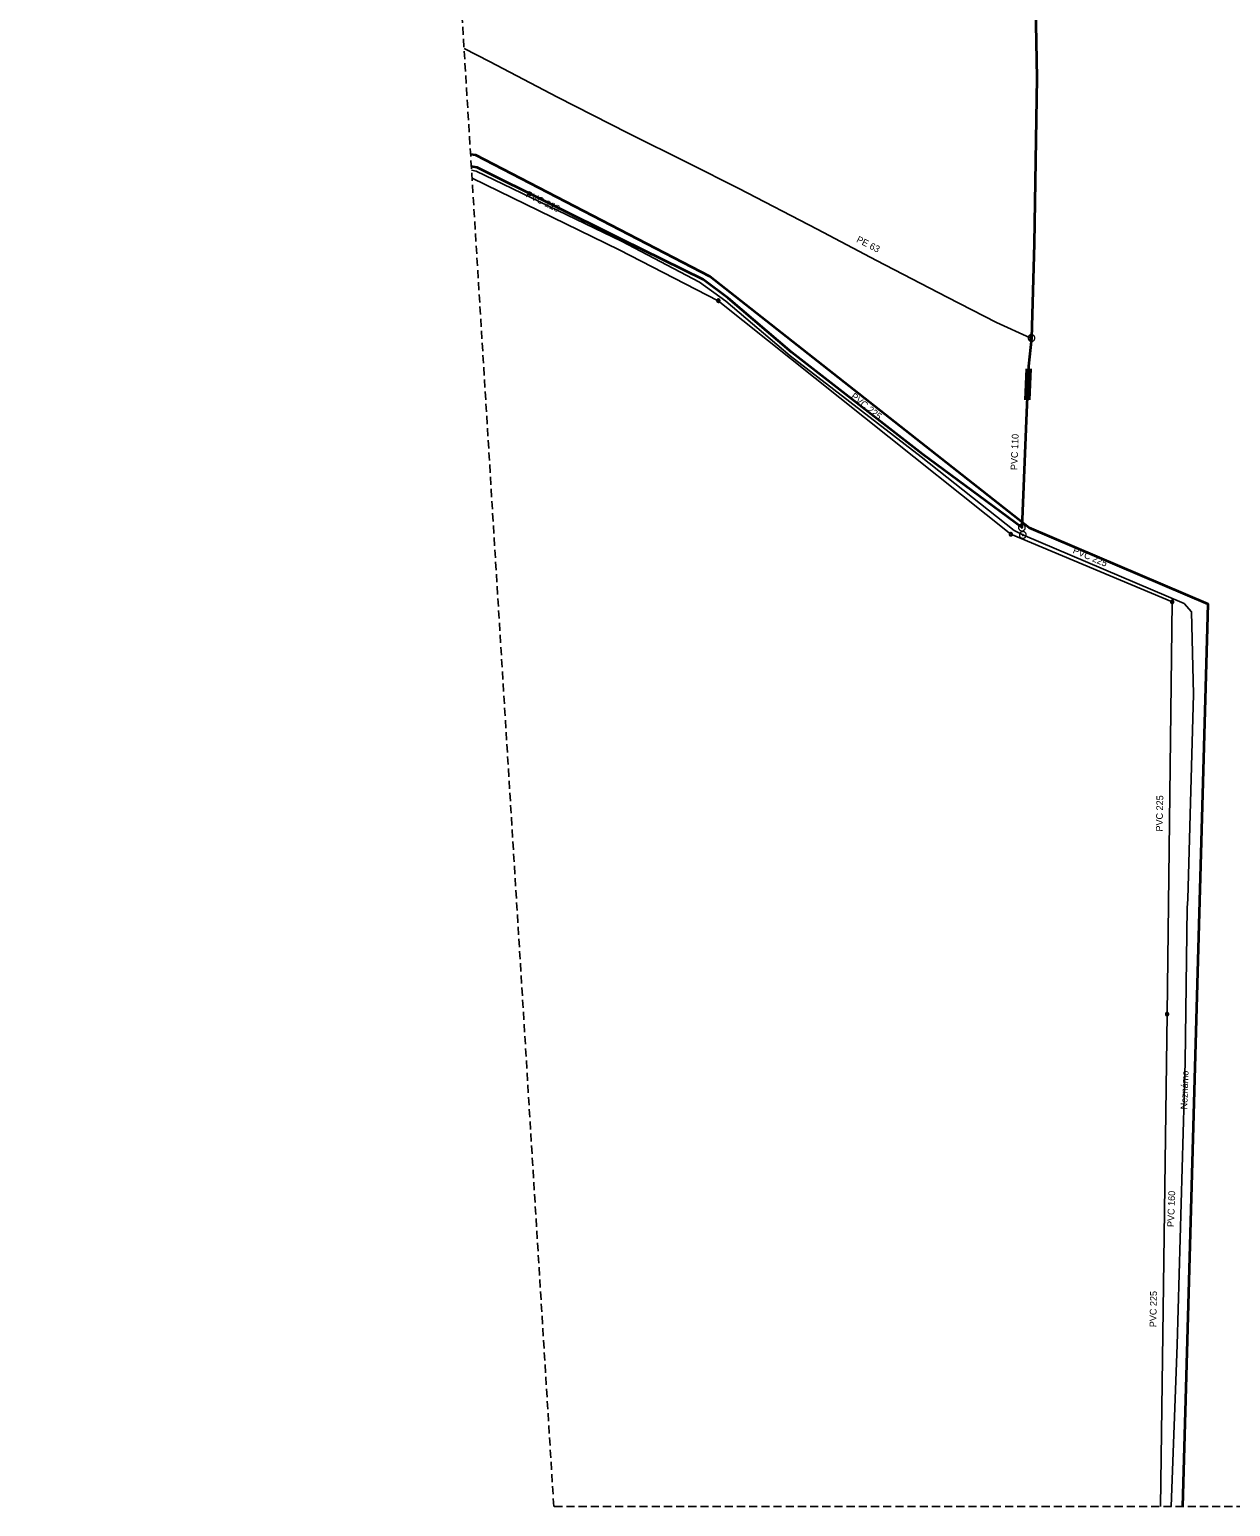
# Model space of a CAD drawing. Extents: x -724325 to -723665, y -972119 to -970722.
# Drawn here: x -723995.2 to -723817.8, y -972118.8 to -971900.7 of the extents above; entities that cross this region are included whole.
import ezdxf

# ---------------------------------------------------------------- set-up
doc = ezdxf.new("R2010")
doc.units = 0
doc.header["$LTSCALE"] = 0.4
doc.linetypes.add('MEDIUM_DASHED', pattern=[4.5, 3, -1.5])
for name, color, linetype, lineweight in [('1', 7, 'Continuous', 25), ('11', 7, 'Continuous', 13), ('14', 7, 'Continuous', 25), ('17', 7, 'Continuous', 35), ('23', 7, 'Continuous', 13), ('3', 7, 'Continuous', 106), ('34', 7, 'Continuous', 13), ('47', 7, 'Continuous', 13)]:
    doc.layers.add(name, color=color, linetype=linetype, lineweight=lineweight)

msp = doc.modelspace()

# ---------------------------------------------------------------- linework, layer by layer
at = {"layer": '1', "linetype": 'MEDIUM_DASHED'}
msp.add_lwpolyline([(-724178.033, -970726.408), (-723849.368, -970722.221), (-723876.582, -971170.211), (-723665.148, -971503.063), (-723686.082, -972118.833), (-723917.752, -972118.833), (-723962.412, -971393.118), (-724325.27, -971133.535)], close=True, dxfattribs=at)
at = {"layer": '11', "lineweight": 35}
msp.add_lwpolyline([(-723824.827, -972118.833), (-723821.07, -971985.522), (-723847.506, -971974.287), (-723894.697, -971937.146), (-723929.265, -971919.226), (-723930.044, -971919.103)], dxfattribs=at)
at = {"layer": '14', "lineweight": 13}
msp.add_line((-723847.171, -971946.223), (-723847.359, -971946.21), dxfattribs=at)
at = {"layer": '17', "lineweight": 25}
for p, q in [((-723893.438, -971940.708), (-723850.218, -971975.219)), ((-723850.218, -971975.219), (-723826.388, -971985.208)), ((-723826.388, -971985.208), (-723827.138, -972046.099)), ((-723827.138, -972046.099), (-723828.091, -972118.833))]:
    msp.add_line(p, q, dxfattribs=at)
at = {"layer": '17'}
for points in [[(-723847.93, -971768.44), (-723847.48, -971775.98), (-723846.969, -971780.5), (-723846.739, -971787.78), (-723847, -971798.309), (-723846.46, -971812.34), (-723846.64, -971835.48), (-723846.67, -971841.969), (-723847.01, -971847.579), (-723846.92, -971878.66), (-723846.399, -971907.809), (-723846.75, -971932.289), (-723847.171, -971946.223)], [(-723848.589, -971974.219), (-723863.28, -971963.399), (-723882.579, -971948.37), (-723891.98, -971940.32), (-723895.699, -971937.59), (-723907.62, -971931.71), (-723929.05, -971921.05), (-723929.933, -971920.901)], [(-723847.171, -971946.223), (-723847.587, -971950.382), (-723847.91, -971957.21), (-723848.589, -971974.219)]]:
    msp.add_lwpolyline(points, dxfattribs=at)
at = {"layer": '17', "lineweight": 25}
for points in [[(-723847.359, -971946.21), (-723852.318, -971943.914), (-723859.614, -971940.173), (-723870.068, -971934.785), (-723878.839, -971930.142), (-723890.425, -971924.131), (-723897.824, -971920.414), (-723906.776, -971915.982), (-723917.208, -971910.62), (-723927.239, -971905.377), (-723931.008, -971903.431)], [(-723929.899, -971921.448), (-723929.23, -971921.559), (-723907.76, -971931.899), (-723896.21, -971937.949), (-723892.34, -971940.76), (-723882.84, -971948.879), (-723863.48, -971963.789), (-723849.71, -971974.66), (-723848.449, -971975.319)], [(-723929.828, -971922.601), (-723908.09, -971933.199), (-723893.438, -971940.708)], [(-723848.449, -971975.319), (-723824.629, -971985.42), (-723823.55, -971986.68), (-723823.239, -971998.829), (-723824.05, -972029.1), (-723824.19, -972030.42), (-723824.44, -972053.219), (-723825.629, -972094.98), (-723826.532, -972118.833)]]:
    msp.add_lwpolyline(points, dxfattribs=at)
at = {"layer": '23'}
for p, q in [((-723893.395, -971940.459), (-723893.483, -971940.966)), ((-723850.175, -971974.97), (-723850.263, -971975.477)), ((-723826.345, -971984.959), (-723826.433, -971985.466)), ((-723827.095, -972045.85), (-723827.183, -972046.357))]:
    msp.add_line(p, q, dxfattribs=at)
for points in [[(-723893.19, -971940.753), (-723893.187, -971940.726), (-723893.186, -971940.7), (-723893.188, -971940.674), (-723893.193, -971940.649), (-723893.2, -971940.622), (-723893.211, -971940.598), (-723893.224, -971940.574), (-723893.238, -971940.554), (-723893.255, -971940.533), (-723893.275, -971940.516), (-723893.296, -971940.5), (-723893.318, -971940.486), (-723893.343, -971940.474), (-723893.368, -971940.467), (-723893.393, -971940.461), (-723893.419, -971940.458), (-723893.446, -971940.456), (-723893.472, -971940.458), (-723893.498, -971940.463), (-723893.523, -971940.47), (-723893.547, -971940.481), (-723893.57, -971940.494), (-723893.592, -971940.508), (-723893.611, -971940.526), (-723893.629, -971940.545), (-723893.646, -971940.567), (-723893.66, -971940.588), (-723893.671, -971940.613), (-723893.68, -971940.638), (-723893.685, -971940.663), (-723893.689, -971940.689), (-723893.69, -971940.715), (-723893.688, -971940.742), (-723893.682, -971940.768), (-723893.674, -971940.794), (-723893.664, -971940.817), (-723893.651, -971940.841), (-723893.638, -971940.862), (-723893.62, -971940.882), (-723893.599, -971940.899), (-723893.579, -971940.916), (-723893.556, -971940.93), (-723893.533, -971940.942), (-723893.508, -971940.95), (-723893.482, -971940.955), (-723893.457, -971940.959), (-723893.43, -971940.96), (-723893.404, -971940.958), (-723893.378, -971940.952), (-723893.352, -971940.945), (-723893.327, -971940.935), (-723893.304, -971940.922), (-723893.283, -971940.908), (-723893.263, -971940.89), (-723893.245, -971940.87), (-723893.229, -971940.849), (-723893.215, -971940.827), (-723893.205, -971940.802), (-723893.197, -971940.778)], [(-723849.97, -971975.264), (-723849.967, -971975.237), (-723849.966, -971975.211), (-723849.968, -971975.185), (-723849.973, -971975.16), (-723849.98, -971975.133), (-723849.991, -971975.109), (-723850.004, -971975.085), (-723850.018, -971975.065), (-723850.035, -971975.044), (-723850.055, -971975.027), (-723850.076, -971975.011), (-723850.098, -971974.997), (-723850.123, -971974.985), (-723850.148, -971974.978), (-723850.173, -971974.972), (-723850.199, -971974.969), (-723850.226, -971974.967), (-723850.252, -971974.969), (-723850.278, -971974.974), (-723850.303, -971974.981), (-723850.327, -971974.992), (-723850.35, -971975.005), (-723850.372, -971975.019), (-723850.391, -971975.037), (-723850.409, -971975.056), (-723850.426, -971975.078), (-723850.44, -971975.099), (-723850.451, -971975.124), (-723850.46, -971975.149), (-723850.465, -971975.174), (-723850.469, -971975.2), (-723850.47, -971975.226), (-723850.468, -971975.253), (-723850.462, -971975.279), (-723850.454, -971975.305), (-723850.444, -971975.328), (-723850.431, -971975.352), (-723850.418, -971975.373), (-723850.4, -971975.393), (-723850.379, -971975.41), (-723850.359, -971975.427), (-723850.336, -971975.441), (-723850.313, -971975.453), (-723850.288, -971975.461), (-723850.262, -971975.466), (-723850.237, -971975.47), (-723850.21, -971975.471), (-723850.184, -971975.469), (-723850.158, -971975.463), (-723850.132, -971975.456), (-723850.107, -971975.446), (-723850.084, -971975.433), (-723850.063, -971975.419), (-723850.043, -971975.401), (-723850.025, -971975.381), (-723850.009, -971975.36), (-723849.995, -971975.338), (-723849.985, -971975.313), (-723849.977, -971975.289)], [(-723826.14, -971985.253), (-723826.137, -971985.226), (-723826.136, -971985.2), (-723826.138, -971985.174), (-723826.143, -971985.149), (-723826.15, -971985.122), (-723826.161, -971985.098), (-723826.174, -971985.074), (-723826.188, -971985.054), (-723826.205, -971985.033), (-723826.225, -971985.016), (-723826.246, -971985), (-723826.268, -971984.986), (-723826.293, -971984.974), (-723826.318, -971984.967), (-723826.343, -971984.961), (-723826.369, -971984.958), (-723826.396, -971984.956), (-723826.422, -971984.958), (-723826.448, -971984.963), (-723826.473, -971984.97), (-723826.497, -971984.981), (-723826.52, -971984.994), (-723826.542, -971985.008), (-723826.561, -971985.026), (-723826.579, -971985.045), (-723826.596, -971985.067), (-723826.61, -971985.088), (-723826.621, -971985.113), (-723826.63, -971985.138), (-723826.635, -971985.163), (-723826.639, -971985.189), (-723826.64, -971985.215), (-723826.638, -971985.242), (-723826.632, -971985.268), (-723826.624, -971985.294), (-723826.614, -971985.317), (-723826.601, -971985.341), (-723826.588, -971985.362), (-723826.57, -971985.382), (-723826.549, -971985.399), (-723826.529, -971985.416), (-723826.506, -971985.43), (-723826.483, -971985.442), (-723826.458, -971985.45), (-723826.432, -971985.455), (-723826.407, -971985.459), (-723826.38, -971985.46), (-723826.354, -971985.458), (-723826.328, -971985.452), (-723826.302, -971985.445), (-723826.277, -971985.435), (-723826.254, -971985.422), (-723826.233, -971985.408), (-723826.213, -971985.39), (-723826.195, -971985.37), (-723826.179, -971985.349), (-723826.165, -971985.327), (-723826.155, -971985.302), (-723826.147, -971985.278)], [(-723826.89, -972046.144), (-723826.887, -972046.117), (-723826.886, -972046.091), (-723826.888, -972046.065), (-723826.893, -972046.04), (-723826.9, -972046.013), (-723826.911, -972045.989), (-723826.924, -972045.965), (-723826.938, -972045.945), (-723826.955, -972045.924), (-723826.975, -972045.907), (-723826.996, -972045.891), (-723827.018, -972045.877), (-723827.043, -972045.865), (-723827.068, -972045.858), (-723827.093, -972045.852), (-723827.119, -972045.849), (-723827.146, -972045.847), (-723827.172, -972045.849), (-723827.198, -972045.854), (-723827.223, -972045.861), (-723827.247, -972045.872), (-723827.27, -972045.885), (-723827.292, -972045.899), (-723827.311, -972045.917), (-723827.329, -972045.936), (-723827.346, -972045.958), (-723827.36, -972045.979), (-723827.371, -972046.004), (-723827.38, -972046.029), (-723827.385, -972046.054), (-723827.389, -972046.08), (-723827.39, -972046.106), (-723827.388, -972046.133), (-723827.382, -972046.159), (-723827.374, -972046.185), (-723827.364, -972046.208), (-723827.351, -972046.232), (-723827.338, -972046.253), (-723827.32, -972046.273), (-723827.299, -972046.29), (-723827.279, -972046.307), (-723827.256, -972046.321), (-723827.233, -972046.333), (-723827.208, -972046.341), (-723827.182, -972046.346), (-723827.157, -972046.35), (-723827.13, -972046.351), (-723827.104, -972046.349), (-723827.078, -972046.343), (-723827.052, -972046.336), (-723827.027, -972046.326), (-723827.004, -972046.313), (-723826.983, -972046.299), (-723826.963, -972046.281), (-723826.945, -972046.261), (-723826.929, -972046.24), (-723826.915, -972046.218), (-723826.905, -972046.193), (-723826.897, -972046.169)]]:
    msp.add_lwpolyline(points, close=True, dxfattribs=at)
at = {"layer": '3'}
msp.add_line((-723847.605, -971950.774), (-723847.824, -971955.379), dxfattribs=at)
at = {"layer": '3', "lineweight": 100}
msp.add_line((-723847.605, -971950.774), (-723847.824, -971955.379), dxfattribs=at)
at = {"layer": '34'}
msp.add_line((-723847.421, -971946.706), (-723847.295, -971945.714), dxfattribs=at)
at = {"layer": '47'}
for points in [[(-723847.186, -971946.722), (-723847.134, -971946.721), (-723847.081, -971946.714), (-723847.031, -971946.702), (-723846.981, -971946.685), (-723846.934, -971946.663), (-723846.889, -971946.635), (-723846.848, -971946.603), (-723846.81, -971946.568), (-723846.776, -971946.529), (-723846.745, -971946.485), (-723846.72, -971946.439), (-723846.7, -971946.391), (-723846.685, -971946.341), (-723846.675, -971946.29), (-723846.671, -971946.238), (-723846.672, -971946.186), (-723846.679, -971946.133), (-723846.691, -971946.082), (-723846.708, -971946.033), (-723846.73, -971945.986), (-723846.758, -971945.941), (-723846.79, -971945.899), (-723846.825, -971945.861), (-723846.864, -971945.827), (-723846.908, -971945.797), (-723846.954, -971945.772), (-723847.002, -971945.751), (-723847.052, -971945.737), (-723847.103, -971945.727), (-723847.155, -971945.723), (-723847.207, -971945.724), (-723847.26, -971945.731), (-723847.311, -971945.742), (-723847.36, -971945.76), (-723847.407, -971945.782), (-723847.452, -971945.809), (-723847.494, -971945.841), (-723847.532, -971945.876), (-723847.566, -971945.916), (-723847.596, -971945.96), (-723847.621, -971946.006), (-723847.642, -971946.053), (-723847.656, -971946.104), (-723847.666, -971946.155), (-723847.67, -971946.207), (-723847.669, -971946.259), (-723847.662, -971946.312), (-723847.651, -971946.362), (-723847.633, -971946.412), (-723847.611, -971946.459), (-723847.584, -971946.504), (-723847.552, -971946.545), (-723847.517, -971946.583), (-723847.477, -971946.617), (-723847.433, -971946.648), (-723847.387, -971946.673), (-723847.34, -971946.693), (-723847.289, -971946.708), (-723847.238, -971946.718)], [(-723847.173, -971946.304), (-723847.164, -971946.305), (-723847.156, -971946.303), (-723847.148, -971946.301), (-723847.14, -971946.298), (-723847.132, -971946.295), (-723847.125, -971946.29), (-723847.117, -971946.285), (-723847.111, -971946.279), (-723847.106, -971946.272), (-723847.101, -971946.266), (-723847.097, -971946.258), (-723847.093, -971946.25), (-723847.091, -971946.242), (-723847.089, -971946.234), (-723847.089, -971946.225), (-723847.088, -971946.216), (-723847.09, -971946.208), (-723847.092, -971946.2), (-723847.095, -971946.192), (-723847.098, -971946.184), (-723847.103, -971946.177), (-723847.108, -971946.169), (-723847.114, -971946.163), (-723847.12, -971946.157), (-723847.127, -971946.153), (-723847.135, -971946.149), (-723847.143, -971946.145), (-723847.151, -971946.143), (-723847.159, -971946.141), (-723847.168, -971946.141), (-723847.177, -971946.14), (-723847.185, -971946.142), (-723847.193, -971946.144), (-723847.201, -971946.147), (-723847.209, -971946.15), (-723847.216, -971946.154), (-723847.224, -971946.16), (-723847.23, -971946.166), (-723847.236, -971946.172), (-723847.24, -971946.179), (-723847.244, -971946.187), (-723847.248, -971946.195), (-723847.25, -971946.203), (-723847.252, -971946.211), (-723847.252, -971946.22), (-723847.253, -971946.229), (-723847.251, -971946.237), (-723847.249, -971946.245), (-723847.246, -971946.253), (-723847.243, -971946.261), (-723847.239, -971946.268), (-723847.233, -971946.276), (-723847.227, -971946.282), (-723847.22, -971946.287), (-723847.214, -971946.292), (-723847.206, -971946.296), (-723847.198, -971946.3), (-723847.19, -971946.302), (-723847.182, -971946.304)], [(-723848.096, -971974.305), (-723848.09, -971974.253), (-723848.089, -971974.2), (-723848.094, -971974.149), (-723848.103, -971974.097), (-723848.119, -971974.047), (-723848.14, -971973.998), (-723848.166, -971973.953), (-723848.196, -971973.911), (-723848.229, -971973.871), (-723848.268, -971973.835), (-723848.31, -971973.803), (-723848.355, -971973.777), (-723848.402, -971973.755), (-723848.452, -971973.738), (-723848.502, -971973.726), (-723848.554, -971973.72), (-723848.607, -971973.719), (-723848.659, -971973.724), (-723848.71, -971973.733), (-723848.76, -971973.749), (-723848.809, -971973.77), (-723848.855, -971973.795), (-723848.897, -971973.825), (-723848.937, -971973.859), (-723848.972, -971973.898), (-723849.004, -971973.94), (-723849.031, -971973.985), (-723849.052, -971974.032), (-723849.069, -971974.082), (-723849.081, -971974.132), (-723849.087, -971974.184), (-723849.088, -971974.237), (-723849.084, -971974.289), (-723849.074, -971974.34), (-723849.058, -971974.39), (-723849.038, -971974.438), (-723849.013, -971974.484), (-723848.983, -971974.527), (-723848.948, -971974.567), (-723848.909, -971974.602), (-723848.867, -971974.634), (-723848.823, -971974.661), (-723848.775, -971974.682), (-723848.725, -971974.699), (-723848.675, -971974.711), (-723848.623, -971974.717), (-723848.57, -971974.718), (-723848.519, -971974.714), (-723848.467, -971974.704), (-723848.417, -971974.688), (-723848.369, -971974.668), (-723848.323, -971974.642), (-723848.281, -971974.612), (-723848.241, -971974.578), (-723848.205, -971974.539), (-723848.173, -971974.497), (-723848.147, -971974.453), (-723848.125, -971974.405), (-723848.108, -971974.355)], [(-723847.956, -971975.405), (-723847.95, -971975.353), (-723847.949, -971975.3), (-723847.954, -971975.249), (-723847.963, -971975.197), (-723847.979, -971975.147), (-723848, -971975.098), (-723848.026, -971975.053), (-723848.056, -971975.011), (-723848.089, -971974.971), (-723848.128, -971974.935), (-723848.17, -971974.903), (-723848.215, -971974.877), (-723848.262, -971974.855), (-723848.312, -971974.838), (-723848.362, -971974.826), (-723848.414, -971974.82), (-723848.467, -971974.819), (-723848.519, -971974.824), (-723848.57, -971974.833), (-723848.62, -971974.849), (-723848.669, -971974.87), (-723848.715, -971974.895), (-723848.757, -971974.925), (-723848.797, -971974.959), (-723848.832, -971974.998), (-723848.864, -971975.04), (-723848.891, -971975.085), (-723848.912, -971975.132), (-723848.929, -971975.182), (-723848.941, -971975.232), (-723848.947, -971975.284), (-723848.948, -971975.337), (-723848.944, -971975.389), (-723848.934, -971975.44), (-723848.918, -971975.49), (-723848.898, -971975.538), (-723848.873, -971975.584), (-723848.843, -971975.627), (-723848.808, -971975.667), (-723848.769, -971975.702), (-723848.727, -971975.734), (-723848.683, -971975.761), (-723848.635, -971975.782), (-723848.585, -971975.799), (-723848.535, -971975.811), (-723848.483, -971975.817), (-723848.43, -971975.818), (-723848.379, -971975.814), (-723848.327, -971975.804), (-723848.277, -971975.788), (-723848.229, -971975.768), (-723848.183, -971975.742), (-723848.141, -971975.712), (-723848.101, -971975.678), (-723848.065, -971975.639), (-723848.033, -971975.597), (-723848.007, -971975.553), (-723847.985, -971975.505), (-723847.968, -971975.455)], [(-723848.508, -971974.233), (-723848.506, -971974.224), (-723848.507, -971974.216), (-723848.507, -971974.207), (-723848.509, -971974.199), (-723848.512, -971974.19), (-723848.515, -971974.183), (-723848.519, -971974.175), (-723848.524, -971974.168), (-723848.53, -971974.162), (-723848.536, -971974.156), (-723848.543, -971974.15), (-723848.55, -971974.146), (-723848.558, -971974.143), (-723848.566, -971974.139), (-723848.574, -971974.138), (-723848.583, -971974.136), (-723848.591, -971974.137), (-723848.6, -971974.137), (-723848.608, -971974.139), (-723848.617, -971974.142), (-723848.624, -971974.145), (-723848.632, -971974.149), (-723848.639, -971974.154), (-723848.646, -971974.16), (-723848.651, -971974.166), (-723848.657, -971974.173), (-723848.661, -971974.18), (-723848.664, -971974.188), (-723848.668, -971974.196), (-723848.669, -971974.204), (-723848.671, -971974.213), (-723848.67, -971974.221), (-723848.67, -971974.23), (-723848.668, -971974.238), (-723848.665, -971974.247), (-723848.663, -971974.254), (-723848.658, -971974.262), (-723848.653, -971974.269), (-723848.647, -971974.276), (-723848.641, -971974.281), (-723848.634, -971974.287), (-723848.627, -971974.291), (-723848.619, -971974.294), (-723848.611, -971974.298), (-723848.603, -971974.299), (-723848.594, -971974.301), (-723848.586, -971974.3), (-723848.577, -971974.3), (-723848.569, -971974.298), (-723848.56, -971974.295), (-723848.553, -971974.293), (-723848.545, -971974.288), (-723848.538, -971974.283), (-723848.532, -971974.277), (-723848.526, -971974.271), (-723848.52, -971974.264), (-723848.516, -971974.257), (-723848.513, -971974.249), (-723848.509, -971974.241)], [(-723848.368, -971975.333), (-723848.366, -971975.324), (-723848.367, -971975.316), (-723848.367, -971975.307), (-723848.369, -971975.299), (-723848.372, -971975.29), (-723848.375, -971975.283), (-723848.379, -971975.275), (-723848.384, -971975.268), (-723848.39, -971975.262), (-723848.396, -971975.256), (-723848.403, -971975.25), (-723848.41, -971975.246), (-723848.418, -971975.243), (-723848.426, -971975.239), (-723848.434, -971975.238), (-723848.443, -971975.236), (-723848.451, -971975.237), (-723848.46, -971975.237), (-723848.468, -971975.239), (-723848.477, -971975.242), (-723848.484, -971975.245), (-723848.492, -971975.249), (-723848.499, -971975.254), (-723848.506, -971975.26), (-723848.511, -971975.266), (-723848.517, -971975.273), (-723848.521, -971975.28), (-723848.524, -971975.288), (-723848.528, -971975.296), (-723848.529, -971975.304), (-723848.531, -971975.313), (-723848.53, -971975.321), (-723848.53, -971975.33), (-723848.528, -971975.338), (-723848.525, -971975.347), (-723848.523, -971975.354), (-723848.518, -971975.362), (-723848.513, -971975.369), (-723848.507, -971975.376), (-723848.501, -971975.381), (-723848.494, -971975.387), (-723848.487, -971975.391), (-723848.479, -971975.394), (-723848.471, -971975.398), (-723848.463, -971975.399), (-723848.454, -971975.401), (-723848.446, -971975.4), (-723848.437, -971975.4), (-723848.429, -971975.398), (-723848.42, -971975.395), (-723848.413, -971975.393), (-723848.405, -971975.388), (-723848.398, -971975.383), (-723848.392, -971975.377), (-723848.386, -971975.371), (-723848.38, -971975.364), (-723848.376, -971975.357), (-723848.373, -971975.349), (-723848.369, -971975.341)]]:
    msp.add_lwpolyline(points, close=True, dxfattribs=at)

# ---------------------------------------------------------------- texts
at = {"layer": '1'}
for s, rotation, p in [('PVC 225 ', 334, (-723921.983, -971925.329)), ('PE 63 ', 333, (-723873.134, -971931.992)), ('PVC 225 ', 321, (-723873.949, -971955.009)), ('PVC 110 ', 88, (-723849.254, -971965.754)), ('PVC 225 ', 337, (-723841.15, -971977.951)), ('PVC 225 ', 89, (-723827.791, -972019.14)), ('Neznámo ', 88, (-723824.159, -972060.186)), ('PVC 160 ', 88, (-723826.118, -972077.569)), ('PVC 225 ', 89, (-723828.728, -972092.36))]:
    msp.add_text(s, height=1, rotation=rotation, dxfattribs=at).set_placement(p)

doc.saveas('drawing.dxf')
